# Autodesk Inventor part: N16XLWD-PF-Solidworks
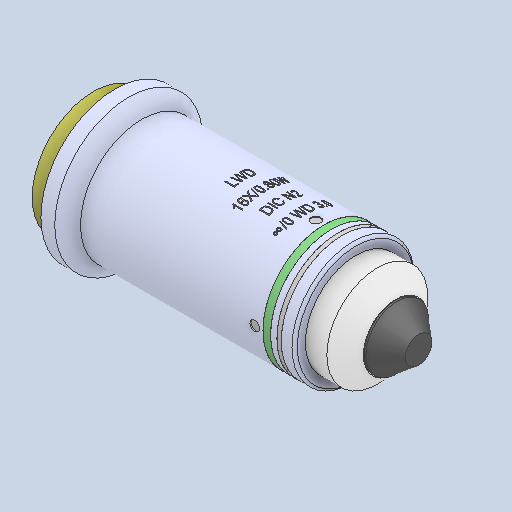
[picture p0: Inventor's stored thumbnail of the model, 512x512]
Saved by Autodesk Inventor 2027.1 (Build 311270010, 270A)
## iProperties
Created: 2012-05
Part Number: N16XLWD-PF-Solidworks
Material: Generic
Document SubType Name: Modeling
Designer: dunge
Density: 1 g/cm^3
Appearance: Default
Author: dunge
Sending System: SOLIDWORKS 2018
Last Saved Date: 2019-08-20
last saved by: agonzalez
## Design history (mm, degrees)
feature "23559-001-1-solid1"
feature "23559-001-1-solid2"
body "Solid1"
body "Solid2"
